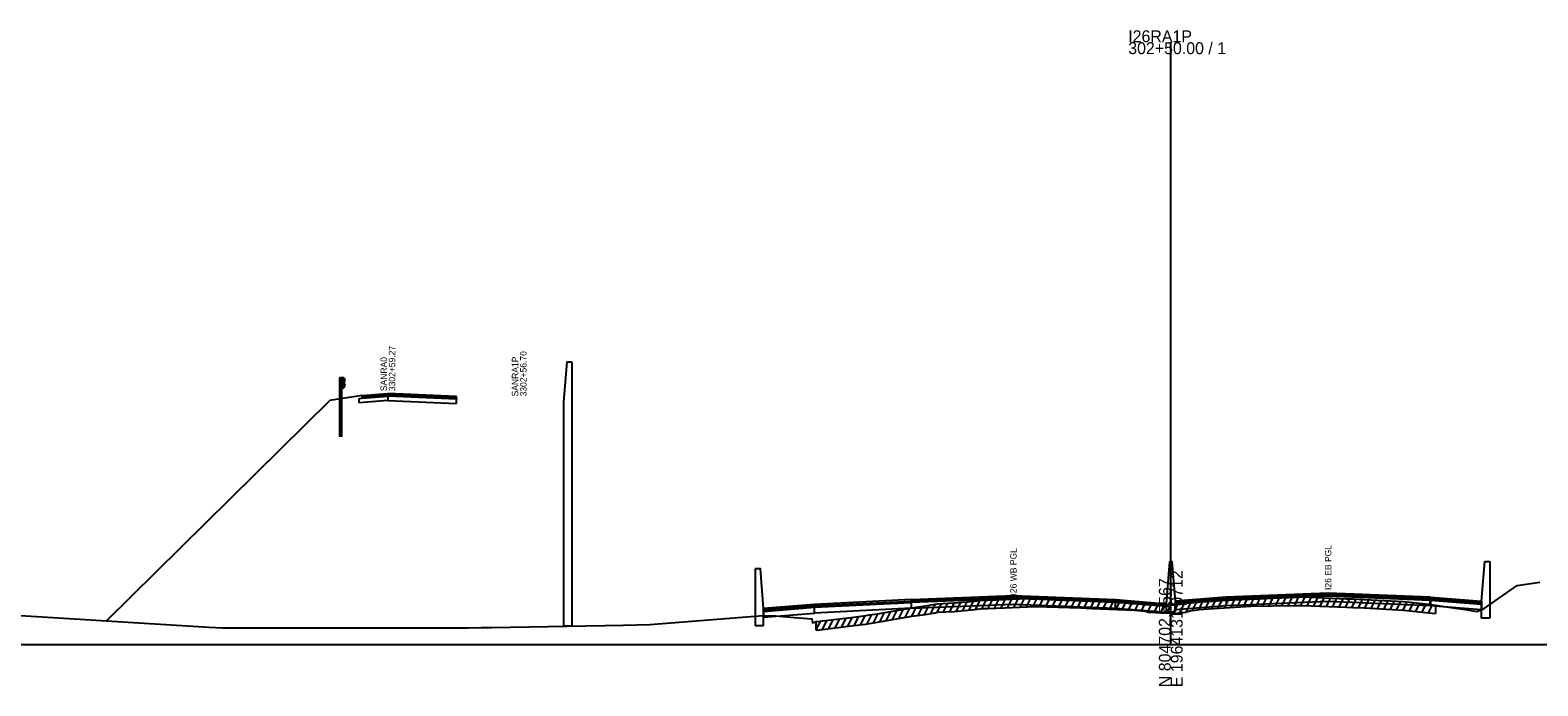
# Model space of a CAD drawing. Extents: x 1017 to 19997, y -1947 to 50737.
# Drawn here: x 12331.9 to 12686.3, y 2490.3 to 2644.5 of the extents above; entities that cross this region are included whole.
import ezdxf

# ---------------------------------------------------------------- set-up
doc = ezdxf.new("R2010")
doc.units = 0
for name, color, linetype in [('RD_GPK_XS_Cell', 7, 'Continuous'), ('RD_XS_Base', 7, 'Continuous'), ('RD_XS_ExGround', 7, 'Continuous'), ('RD_XS_ExPaveRet', 7, 'Continuous'), ('RD_XS_GR', 7, 'Continuous'), ('RD_XS_Greenside', 7, 'Continuous'), ('RD_XS_MedBWall', 7, 'Continuous'), ('RD_XS_Pave', 7, 'Continuous'), ('RD_XS_PaveOvlay', 7, 'Continuous'), ('RD_XS_TX_Notes', 7, 'Continuous')]:
    doc.layers.add(name, color=color, linetype=linetype)

msp = doc.modelspace()

# ---------------------------------------------------------------- linework, layer by layer
at = {"layer": 'RD_GPK_XS_Cell'}
for p, q in [((12600, 2500), (12600, 2641.68)), ((12000, 2500), (12600, 2500)), ((12600, 2500), (13200, 2500))]:
    msp.add_line(p, q, dxfattribs=at)
at = {"layer": 'RD_XS_Base'}
for points in [[(12409.18, 2557.9), (12409.89, 2557.95), (12415.95, 2558.41)], [(12409.18, 2556.9), (12409.18, 2557.9)], [(12415.95, 2557.41), (12409.18, 2556.9)], [(12432.12, 2557.72), (12415.95, 2558.41)], [(12415.95, 2558.41), (12415.95, 2557.41)], [(12415.95, 2557.41), (12432.12, 2556.72)], [(12432.12, 2556.72), (12432.12, 2557.72)], [(12516.27, 2508.78), (12539, 2509.91)], [(12587, 2509.92), (12563, 2510.89), (12539, 2509.91)], [(12539, 2509.91), (12539, 2508.57)], [(12539, 2508.57), (12563, 2509.55), (12587, 2508.58)], [(12587, 2508.58), (12587, 2509.92)], [(12599, 2508.98), (12587, 2509.92)], [(12601, 2509.56), (12613, 2510.5)], [(12601, 2508.22), (12601, 2509.56)], [(12613, 2510.5), (12637, 2511.46), (12661, 2510.5)], [(12613, 2510.5), (12613, 2509.16)], [(12661, 2509.16), (12637, 2510.12), (12613, 2509.16)], [(12661, 2510.5), (12661.05, 2510.49)], [(12661, 2509.16), (12661, 2510.5)], [(12661.05, 2510.49), (12673.05, 2509.53)], [(12661.05, 2509.15), (12661.05, 2510.49)], [(12661.05, 2510.49), (12661.05, 2509.15)], [(12673.05, 2509.53), (12673.05, 2508.19)], [(12516.27, 2508.78), (12504.27, 2507.82)], [(12504.27, 2507.82), (12504.27, 2506.48)], [(12504.27, 2506.48), (12516.27, 2507.44)], [(12516.27, 2507.44), (12516.27, 2508.78)], [(12539, 2508.57), (12516.27, 2507.44)], [(12587, 2508.58), (12599, 2507.64)], [(12599, 2507.64), (12599, 2508.98)], [(12613, 2509.16), (12601, 2508.22)], [(12661.05, 2509.15), (12661, 2509.16)], [(12673.05, 2508.19), (12661.05, 2509.15)]]:
    msp.add_lwpolyline(points, dxfattribs=at)
at = {"layer": 'RD_XS_ExGround'}
msp.add_lwpolyline([(12329.57, 2506.89), (12373.89, 2504.12), (12377.08, 2503.94), (12377.95, 2503.95), (12434.89, 2503.94), (12437.94, 2504.01), (12440.38, 2504.05), (12471.34, 2504.62), (12477.55, 2504.74), (12504.27, 2506.85), (12507.16, 2506.74), (12508.88, 2506.6), (12511.55, 2506.36), (12515.62, 2506.04), (12515.74, 2505.14), (12516.23, 2505.27), (12516.6, 2505.43), (12518.11, 2505.58), (12524.89, 2506.4), (12528.31, 2506.82), (12529.18, 2506.98), (12531.03, 2507.27), (12539.15, 2508.66), (12542.3, 2509.12), (12544.65, 2509.5), (12545.16, 2509.6), (12549.05, 2509.82), (12553.83, 2510.23), (12555.79, 2510.48), (12556.97, 2510.49), (12560.94, 2510.65), (12568.21, 2510.95), (12578.86, 2510.62), (12580.12, 2510.58), (12581.48, 2510.53), (12591.45, 2510.12), (12593.88, 2509.87), (12594.29, 2509.83), (12594.74, 2509.65), (12596.4, 2509.58), (12597.68, 2509.51), (12598.63, 2509.47), (12600, 2509.39), (12600.66, 2509.35), (12602.36, 2509.49), (12603.6, 2509.6), (12603.87, 2509.83), (12604.11, 2509.79), (12604.41, 2509.97), (12606.25, 2510.21), (12606.71, 2510.27), (12608.9, 2510.41), (12618.79, 2511.02), (12629.09, 2511.2), (12630.91, 2511.23), (12641.31, 2510.81), (12642.79, 2510.75), (12645.45, 2510.62), (12654.69, 2510.14), (12660.65, 2509.5), (12662.25, 2509.32), (12666.38, 2508.67), (12669.18, 2508.25), (12671.97, 2507.79), (12673.7, 2508.51), (12681.42, 2513.88), (12686.74, 2514.67)], dxfattribs=at)
at = {"layer": 'RD_XS_ExPaveRet'}
for p, q in [((12543.6, 2507.33), (12544.69, 2509.5)), ((12545.1, 2507.59), (12546.13, 2509.66)), ((12546.6, 2507.68), (12547.63, 2509.74)), ((12548.1, 2507.77), (12549.13, 2509.83)), ((12549.6, 2507.87), (12550.65, 2509.96)), ((12551.1, 2508), (12552.15, 2510.08)), ((12552.6, 2508.12), (12553.65, 2510.21)), ((12554.1, 2508.26), (12555.17, 2510.4)), ((12555.6, 2508.46), (12556.62, 2510.49)), ((12557.1, 2508.5), (12558.12, 2510.54)), ((12558.6, 2508.56), (12559.62, 2510.6)), ((12560.1, 2508.62), (12561.12, 2510.66)), ((12561.6, 2508.68), (12562.62, 2510.72)), ((12563.1, 2508.74), (12564.12, 2510.78)), ((12564.6, 2508.8), (12565.62, 2510.84)), ((12566.1, 2508.86), (12567.12, 2510.91)), ((12567.6, 2508.93), (12568.61, 2510.94)), ((12569.1, 2508.92), (12570.09, 2510.89)), ((12570.6, 2508.88), (12571.59, 2510.84)), ((12572.1, 2508.83), (12573.09, 2510.8)), ((12573.6, 2508.78), (12574.59, 2510.75)), ((12575.1, 2508.73), (12576.09, 2510.7)), ((12576.6, 2508.69), (12577.59, 2510.66)), ((12578.1, 2508.64), (12579.09, 2510.61)), ((12579.6, 2508.6), (12580.58, 2510.56)), ((12581.1, 2508.54), (12582.08, 2510.5)), ((12582.6, 2508.48), (12583.58, 2510.44)), ((12584.1, 2508.42), (12585.08, 2510.38)), ((12585.6, 2508.36), (12586.58, 2510.32)), ((12587.1, 2508.3), (12588.08, 2510.26)), ((12588.6, 2508.24), (12589.58, 2510.2)), ((12590.1, 2508.18), (12591.08, 2510.14)), ((12591.6, 2508.11), (12592.55, 2510.01)), ((12593.1, 2507.95), (12594.05, 2509.85)), ((12594.6, 2507.71), (12595.56, 2509.62)), ((12596.1, 2507.59), (12597.08, 2509.54)), ((12602.1, 2507.47), (12603.15, 2509.56)), ((12603.6, 2507.6), (12604.81, 2510.02)), ((12605.1, 2508.06), (12606.17, 2510.2)), ((12606.6, 2508.26), (12607.64, 2510.33)), ((12608.1, 2508.36), (12609.13, 2510.42)), ((12609.6, 2508.45), (12610.63, 2510.52)), ((12611.1, 2508.55), (12612.13, 2510.61)), ((12612.6, 2508.64), (12613.63, 2510.7)), ((12614.1, 2508.73), (12615.13, 2510.8)), ((12615.6, 2508.83), (12616.63, 2510.89)), ((12617.1, 2508.92), (12618.13, 2510.98)), ((12618.6, 2509.01), (12619.61, 2511.04)), ((12620.1, 2509.05), (12621.11, 2511.06)), ((12621.6, 2509.07), (12622.61, 2511.09)), ((12623.1, 2509.1), (12624.11, 2511.11)), ((12624.6, 2509.12), (12625.61, 2511.14)), ((12626.1, 2509.15), (12627.11, 2511.17)), ((12627.6, 2509.17), (12628.61, 2511.19)), ((12629.1, 2509.2), (12630.11, 2511.22)), ((12630.6, 2509.23), (12631.59, 2511.21)), ((12632.1, 2509.19), (12633.08, 2511.15)), ((12633.6, 2509.12), (12634.58, 2511.09)), ((12635.1, 2509.06), (12636.08, 2511.03)), ((12636.6, 2509), (12637.58, 2510.96)), ((12638.1, 2508.94), (12639.08, 2510.9)), ((12639.6, 2508.88), (12640.58, 2510.84)), ((12641.1, 2508.82), (12642.08, 2510.78)), ((12642.6, 2508.75), (12643.58, 2510.71)), ((12644.1, 2508.68), (12645.08, 2510.63)), ((12645.6, 2508.61), (12646.58, 2510.56)), ((12647.1, 2508.53), (12648.08, 2510.48)), ((12648.6, 2508.45), (12649.58, 2510.4)), ((12650.1, 2508.37), (12651.08, 2510.32)), ((12651.6, 2508.3), (12652.58, 2510.25)), ((12653.1, 2508.22), (12654.08, 2510.17)), ((12654.6, 2508.14), (12655.55, 2510.04)), ((12656.1, 2507.98), (12657.05, 2509.88)), ((12657.6, 2507.82), (12658.55, 2509.72)), ((12659.1, 2507.66), (12660.05, 2509.56)), ((12521.1, 2503.94), (12522.17, 2506.07)), ((12522.6, 2504.13), (12523.67, 2506.26)), ((12524.1, 2504.31), (12525.17, 2506.44)), ((12525.6, 2504.49), (12526.67, 2506.62)), ((12527.1, 2504.68), (12528.17, 2506.81)), ((12528.6, 2504.88), (12529.69, 2507.06)), ((12530.1, 2505.12), (12531.19, 2507.3)), ((12531.03, 2505.27), (12539.15, 2506.66)), ((12531.6, 2505.37), (12532.69, 2507.56)), ((12533.1, 2505.62), (12534.19, 2507.81)), ((12534.6, 2505.88), (12535.69, 2508.07)), ((12536.1, 2506.14), (12537.19, 2508.32)), ((12537.6, 2506.39), (12538.69, 2508.58)), ((12539.1, 2506.65), (12540.18, 2508.81)), ((12539.15, 2506.66), (12542.3, 2507.12)), ((12540.6, 2506.87), (12541.68, 2509.03)), ((12542.1, 2507.09), (12543.19, 2509.26)), ((12542.3, 2507.12), (12544.65, 2507.5)), ((12544.65, 2507.5), (12545.16, 2507.6)), ((12545.16, 2507.6), (12549.05, 2507.82)), ((12549.05, 2507.82), (12553.83, 2508.23)), ((12553.83, 2508.23), (12555.79, 2508.48)), ((12555.79, 2508.48), (12556.97, 2508.49)), ((12556.97, 2508.49), (12560.94, 2508.65)), ((12560.94, 2508.65), (12568.21, 2508.95)), ((12568.21, 2508.95), (12578.86, 2508.62)), ((12578.86, 2508.62), (12580.12, 2508.58)), ((12580.12, 2508.58), (12581.48, 2508.53)), ((12581.48, 2508.53), (12591.45, 2508.12)), ((12591.45, 2508.12), (12593.88, 2507.87)), ((12593.88, 2507.87), (12594.29, 2507.83)), ((12594.29, 2507.83), (12594.74, 2507.65)), ((12594.74, 2507.65), (12596.4, 2507.58)), ((12596.4, 2507.58), (12597.68, 2507.51)), ((12597.6, 2507.51), (12598.58, 2509.47)), ((12597.68, 2507.51), (12598.63, 2507.47)), ((12598.63, 2507.47), (12600, 2507.39)), ((12599.1, 2507.44), (12600.07, 2509.38)), ((12600, 2507.39), (12600.66, 2507.35)), ((12600.6, 2507.35), (12601.64, 2509.43)), ((12600.66, 2507.35), (12602.36, 2507.49)), ((12602.36, 2507.49), (12603.6, 2507.6)), ((12603.6, 2507.6), (12603.87, 2507.83)), ((12603.87, 2507.83), (12604.11, 2507.79)), ((12604.11, 2507.79), (12604.41, 2507.97)), ((12604.41, 2507.97), (12606.25, 2508.21)), ((12606.25, 2508.21), (12606.71, 2508.27)), ((12606.71, 2508.27), (12608.9, 2508.41)), ((12608.9, 2508.41), (12618.79, 2509.02)), ((12618.79, 2509.02), (12629.09, 2509.2)), ((12629.09, 2509.2), (12630.91, 2509.23)), ((12630.91, 2509.23), (12641.31, 2508.81)), ((12641.31, 2508.81), (12642.79, 2508.75)), ((12642.79, 2508.75), (12645.45, 2508.62)), ((12645.45, 2508.62), (12654.69, 2508.14)), ((12654.69, 2508.14), (12660.65, 2507.5)), ((12660.6, 2507.5), (12661.55, 2509.4)), ((12660.65, 2507.5), (12662.25, 2507.32)), ((12662.25, 2509.32), (12662.25, 2507.32)), ((12516.6, 2503.43), (12517.65, 2505.54)), ((12516.6, 2503.43), (12516.6, 2505.43)), ((12516.6, 2503.43), (12518.11, 2503.58)), ((12518.1, 2503.58), (12519.17, 2505.71)), ((12518.11, 2503.58), (12524.89, 2504.4)), ((12519.6, 2503.76), (12520.67, 2505.89)), ((12524.89, 2504.4), (12528.31, 2504.82)), ((12528.31, 2504.82), (12529.18, 2504.98)), ((12529.18, 2504.98), (12531.03, 2505.27))]:
    msp.add_line(p, q, dxfattribs=at)
at = {"layer": 'RD_XS_GR'}
for points in [[(12405.11, 2562.77), (12404.61, 2562.77)], [(12404.61, 2562.77), (12404.61, 2557.77)], [(12405.11, 2557.85), (12405.11, 2562.77)], [(12405.6, 2562.77), (12405.11, 2562.77)], [(12405.11, 2562.77), (12405.11, 2560.41)], [(12405.6, 2560.41), (12405.6, 2562.77)], [(12405.6, 2562.77), (12405.85, 2562.17)], [(12405.11, 2560.41), (12405.6, 2560.41)], [(12405.85, 2561.01), (12405.6, 2560.41)], [(12405.85, 2562.17), (12405.61, 2561.57)], [(12405.61, 2561.57), (12405.85, 2561.01)], [(12404.61, 2557.77), (12405.11, 2557.85)], [(12404.61, 2557.77), (12404.61, 2548.85)], [(12405.11, 2548.85), (12405.11, 2557.85)]]:
    msp.add_lwpolyline(points, dxfattribs=at)
at = {"layer": 'RD_XS_Greenside'}
for points in [[(12405.85, 2557.96), (12402.31, 2557.42), (12349.73, 2505.56)], [(12409.89, 2558.59), (12405.85, 2557.96)]]:
    msp.add_lwpolyline(points, dxfattribs=at)
at = {"layer": 'RD_XS_MedBWall'}
for points in [[(12459.31, 2566.42), (12458, 2566.41), (12457.21, 2557.07)], [(12459.31, 2504.44), (12459.31, 2566.42)], [(12457.21, 2557.07), (12457.21, 2504.45)], [(12504.27, 2508.5), (12503.52, 2517.84), (12502.27, 2517.84)], [(12502.27, 2517.84), (12502.27, 2504.5)], [(12599, 2509.63), (12599.75, 2519.55), (12600.25, 2519.55), (12601, 2510.21)], [(12673.05, 2510.21), (12673.8, 2519.55), (12675.05, 2519.55)], [(12675.05, 2519.55), (12675.05, 2506.21)], [(12599, 2507.63), (12599, 2509.63)], [(12601, 2510.21), (12601, 2507.63)], [(12673.05, 2506.21), (12673.05, 2510.21)], [(12504.27, 2504.5), (12504.27, 2508.5)], [(12601, 2507.63), (12599, 2507.63)], [(12675.05, 2506.21), (12673.05, 2506.21)], [(12457.21, 2504.45), (12459.31, 2504.44)], [(12502.27, 2504.5), (12504.27, 2504.5)]]:
    msp.add_lwpolyline(points, dxfattribs=at)
at = {"layer": 'RD_XS_Pave'}
for points in [[(12409.89, 2558.27), (12415.95, 2558.73)], [(12415.95, 2558.41), (12409.89, 2557.95)], [(12409.89, 2557.95), (12409.89, 2558.27)], [(12415.95, 2558.41), (12415.95, 2558.73)], [(12415.95, 2558.73), (12432.12, 2558.03)], [(12432.12, 2557.72), (12415.95, 2558.41)], [(12432.12, 2558.03), (12432.12, 2557.72)], [(12516.27, 2509.12), (12539, 2510.25)], [(12539, 2509.91), (12516.27, 2508.78)], [(12539, 2510.25), (12563, 2511.22), (12587, 2510.26)], [(12587, 2509.92), (12563, 2510.89), (12539, 2509.91)], [(12539, 2509.91), (12539, 2510.25)], [(12587, 2510.26), (12599, 2509.32)], [(12587, 2509.92), (12587, 2510.26)], [(12599, 2508.98), (12587, 2509.92)], [(12613, 2510.84), (12601, 2509.9)], [(12601, 2509.56), (12613, 2510.5)], [(12601, 2509.9), (12601, 2509.56)], [(12661, 2510.84), (12637, 2511.8), (12613, 2510.84)], [(12613, 2510.5), (12637, 2511.46), (12661, 2510.5)], [(12613, 2510.84), (12613, 2510.5)], [(12661, 2510.84), (12661.05, 2510.83)], [(12661, 2510.5), (12661, 2510.84)], [(12661.05, 2510.49), (12661, 2510.5)], [(12661.05, 2510.83), (12673.05, 2509.87)], [(12661.05, 2510.49), (12661.05, 2510.83)], [(12661.05, 2510.83), (12661.05, 2510.49)], [(12673.05, 2509.53), (12661.05, 2510.49)], [(12673.05, 2509.87), (12673.05, 2509.53)], [(12516.27, 2509.12), (12504.27, 2508.16)], [(12504.27, 2507.82), (12516.27, 2508.78)], [(12504.27, 2508.16), (12504.27, 2507.82)], [(12516.27, 2508.78), (12516.27, 2509.12)], [(12599, 2509.32), (12599, 2508.98)]]:
    msp.add_lwpolyline(points, dxfattribs=at)
at = {"layer": 'RD_XS_PaveOvlay'}
for points in [[(12409.89, 2558.59), (12415.95, 2559.05)], [(12415.95, 2558.73), (12409.89, 2558.27)], [(12409.89, 2558.27), (12409.89, 2558.59)], [(12432.12, 2558.35), (12415.95, 2559.05)], [(12415.95, 2559.05), (12415.95, 2558.73)], [(12415.95, 2558.73), (12432.12, 2558.03)], [(12432.12, 2558.03), (12432.12, 2558.35)], [(12539, 2510.59), (12516.27, 2509.46)], [(12516.27, 2509.12), (12539, 2510.25)], [(12539, 2510.59), (12563, 2511.55), (12587, 2510.59)], [(12587, 2510.26), (12563, 2511.22), (12539, 2510.25)], [(12539, 2510.25), (12539, 2510.59)], [(12587, 2510.59), (12599, 2509.63)], [(12587, 2510.26), (12587, 2510.59)], [(12599, 2509.32), (12587, 2510.26)], [(12599, 2509.63), (12599, 2509.32)], [(12613, 2511.17), (12601, 2510.21)], [(12601, 2509.9), (12613, 2510.84)], [(12601, 2510.21), (12601, 2509.9)], [(12661, 2511.17), (12637, 2512.13), (12613, 2511.17)], [(12613, 2510.84), (12637, 2511.8), (12661, 2510.84)], [(12613, 2511.17), (12613, 2510.84)], [(12661, 2510.84), (12661, 2511.17)], [(12661, 2511.17), (12661.05, 2511.17)], [(12661.05, 2510.83), (12661, 2510.84)], [(12661.05, 2511.17), (12673.05, 2510.21)], [(12661.05, 2510.83), (12661.05, 2511.17)], [(12661.05, 2511.17), (12661.05, 2510.83)], [(12673.05, 2509.87), (12661.05, 2510.83)], [(12673.05, 2510.21), (12673.05, 2509.87)], [(12516.27, 2509.46), (12504.27, 2508.5)], [(12504.27, 2508.16), (12516.27, 2509.12)], [(12504.27, 2508.5), (12504.27, 2508.16)], [(12516.27, 2509.12), (12516.27, 2509.46)]]:
    msp.add_lwpolyline(points, dxfattribs=at)

# ---------------------------------------------------------------- texts
at = {"layer": 'RD_GPK_XS_Cell'}
for s, p in [('I26RA1P', (12590, 2641.68)), ('302+50.00 / 1', (12590, 2638.88))]:
    msp.add_text(s, height=2.8, dxfattribs=at).set_placement(p)
for s, p in [('E 1964131.0712', (12602.8, 2490)), ('N 804702.5567', (12600, 2490))]:
    msp.add_text(s, height=2.8, rotation=90, dxfattribs=at).set_placement(p)
at = {"layer": 'RD_XS_TX_Notes'}
for s, p in [(' 3302+59.27', (12417.68, 2559.06)), (' SANRA0', (12415.72, 2559.06)), (' SANRA1P', (12446.59, 2557.82)), (' 3302+56.70', (12448.55, 2557.82)), ('I26 WB PGL', (12563.75, 2511.55)), ('I26 EB PGL', (12637.75, 2512.86))]:
    msp.add_text(s, height=1.5, rotation=90, dxfattribs=at).set_placement(p)

doc.saveas('drawing.dxf')
